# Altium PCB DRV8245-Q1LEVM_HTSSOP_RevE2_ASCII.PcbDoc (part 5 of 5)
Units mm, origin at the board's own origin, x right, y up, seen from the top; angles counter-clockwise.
Board outline 81.9 x 103.6 mm, 4 copper layers (Top Layer, Signal Layer 1, Signal Layer 2, Bottom Layer), stack 1.554 mm thick; 187 components, 116 nets, 590 pads, 1182 vias.
Unrouted connection lines stored in the file: 116.
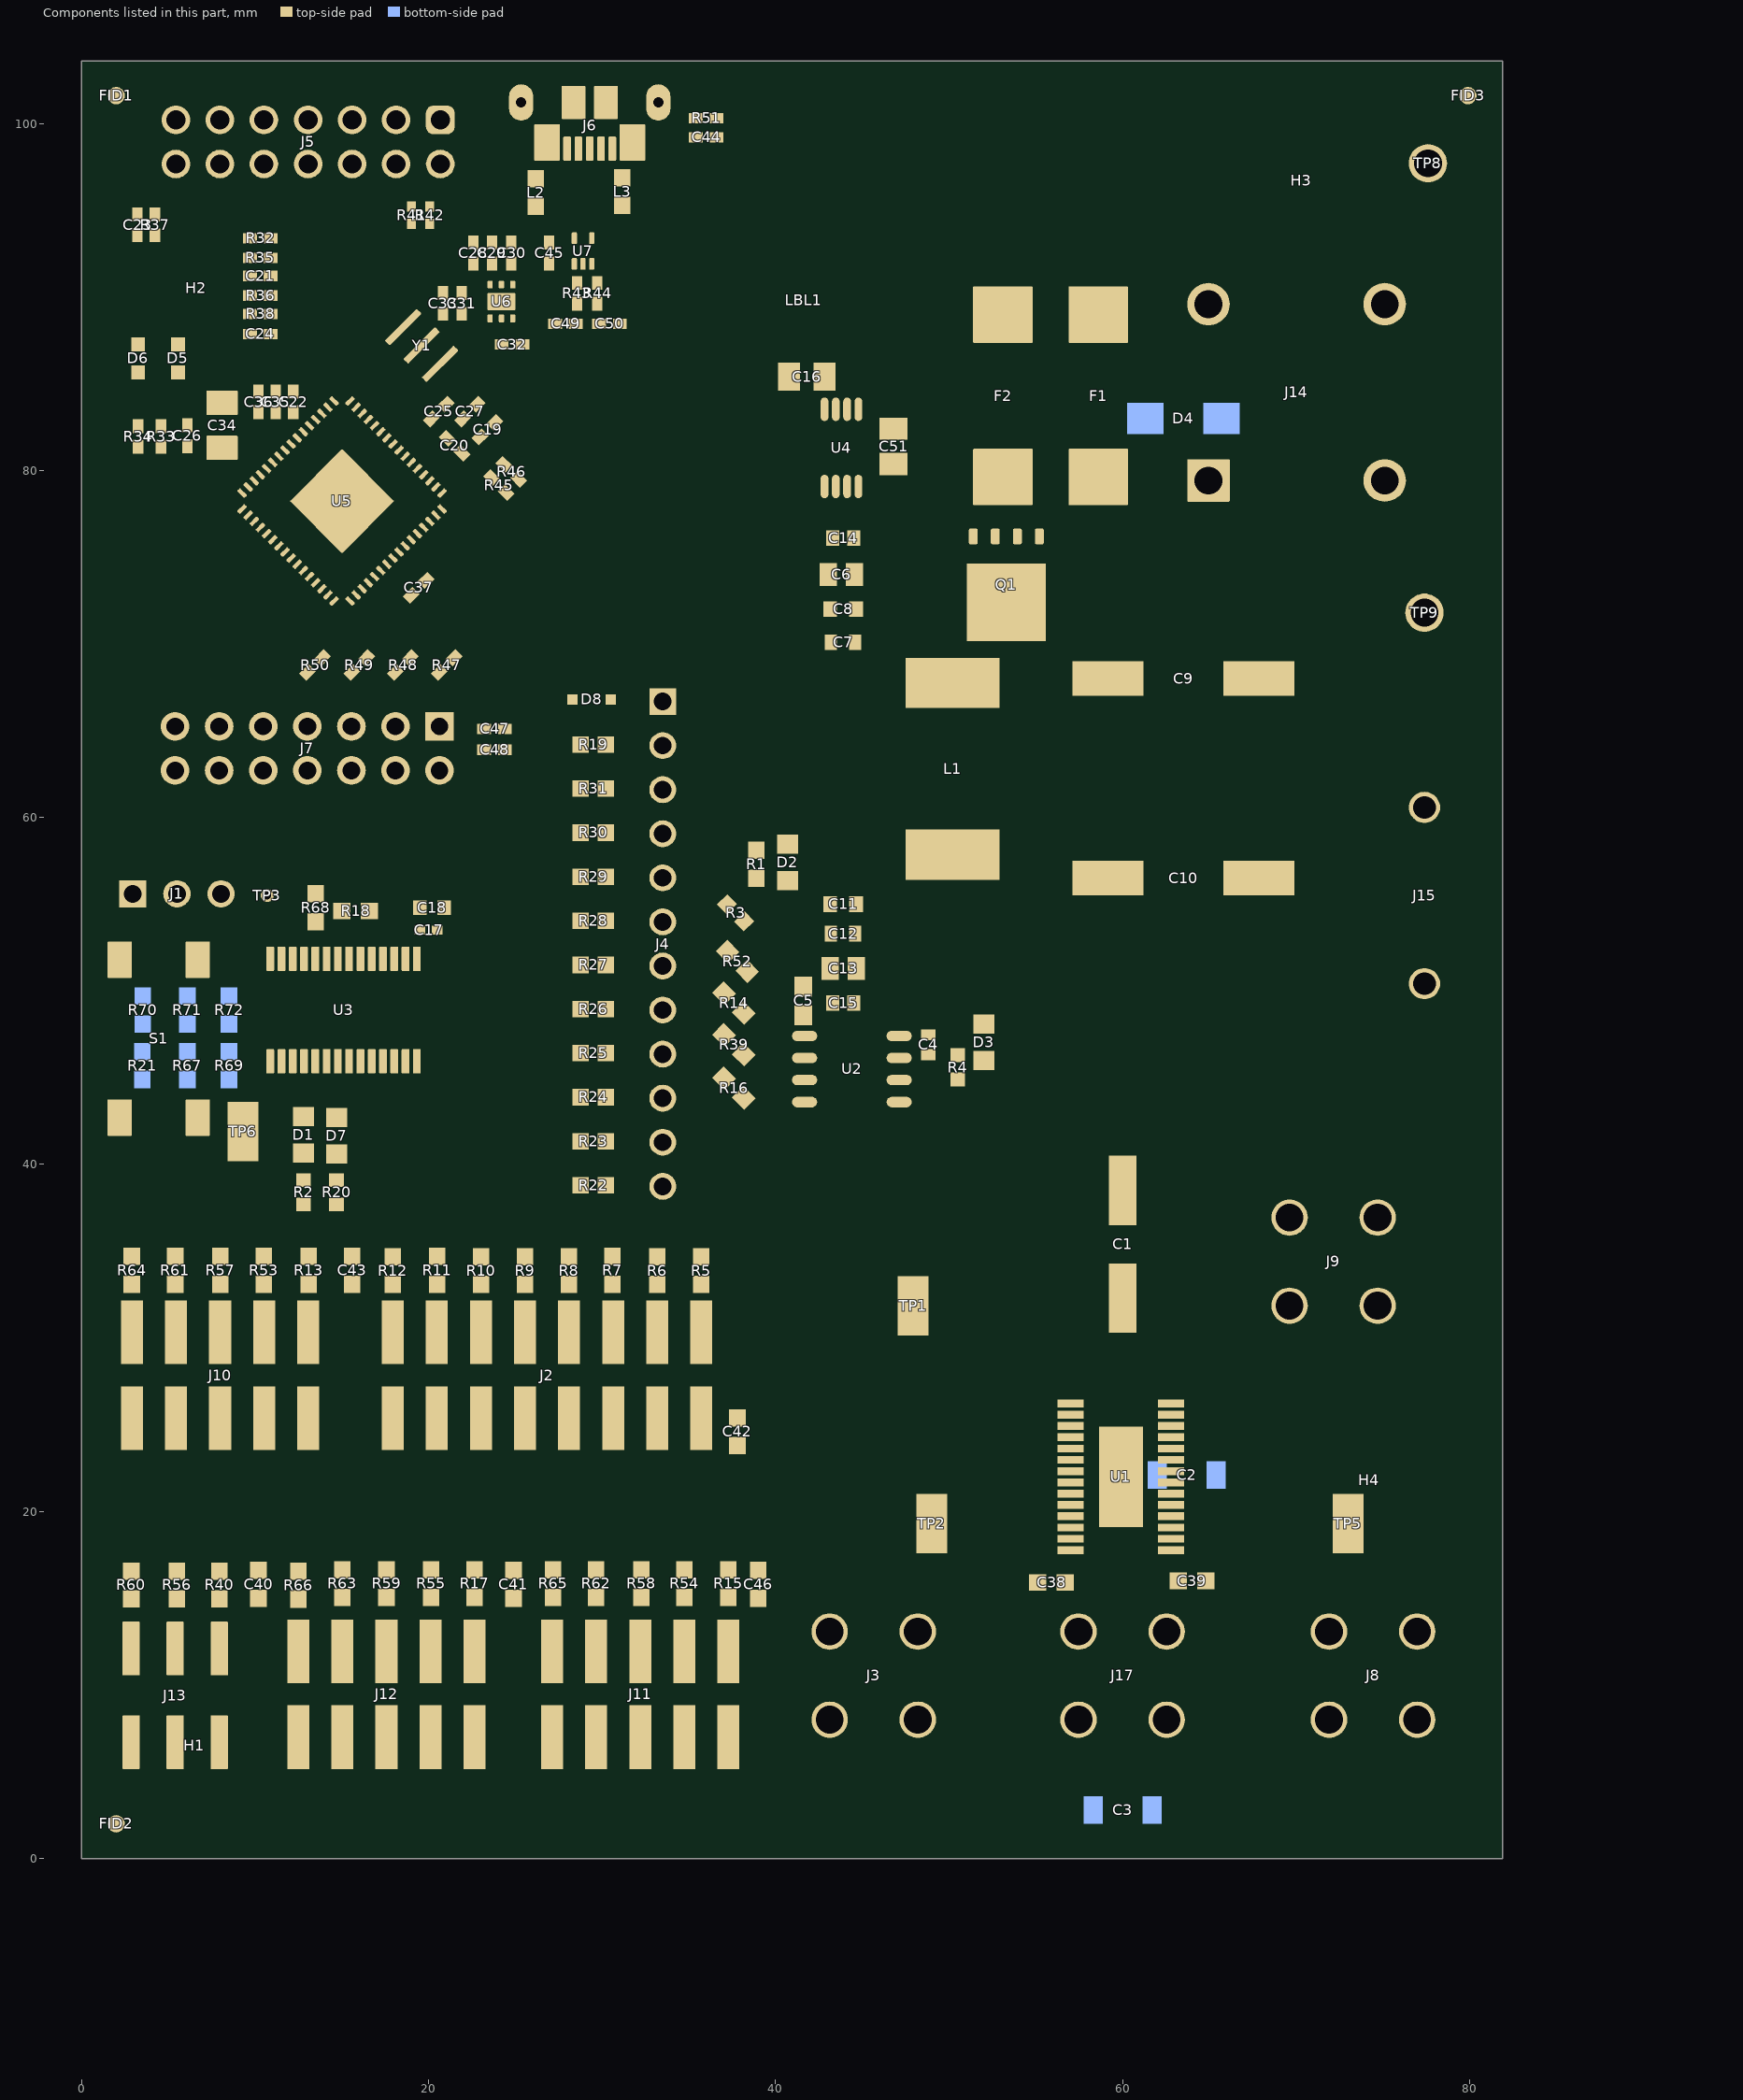
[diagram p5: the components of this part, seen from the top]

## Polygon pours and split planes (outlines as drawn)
VM on Top Layer "TOP_LAYER_NONET_P-001" (solid, pour order 239): 52.9,47.1 56.1,47.1 56.1,43.7
VM on Top Layer "TOP_LAYER_VM_P125" (solid, pour order 125): 40,21.5 80,21.5 80,42 63.2,42 63.2,60.5 44,60.5 44,47.1 56.1,47.1 56.1,42 40,42
GND on Top Layer "TOP_LAYER_GND_P237" (solid, remove dead copper, pour order 237): 0,0 81.9,0 81.9,103.6 0,103.6
GND on Top Layer "TOP_LAYER_GND_P086" (solid, pour order 86): 56,35.5 63.9,35.5 63.9,2 56,2
OUT2 on Top Layer "TOP_LAYER_OUT2_P173" (solid, pour order 173): 62.1,21.4 62.1,19.4 63.9,19.4 63.9,2 80,2 80,21.4
OUT1 on Top Layer "TOP_LAYER_OUT1_P129" (solid, pour order 129): 58,21.3 58,19.4 56,19.4 56,2 39.9,2 39.9,21.3
P_IN on Top Layer "TOP_LAYER_P_IN_P227" (solid, pour order 227): 63.2,60.7 63.2,79.8 44,79.8 44,60.7
VBAT on Top Layer "TOP_LAYER_VBAT_P223" (solid, pour order 223): 63.2,84.4 63.2,75.3 48.3,75.3 48.3,84.4
NetF1_2 on Top Layer "TOP_LAYER_NETF1_2_P207" (solid, pour order 207): 48.2,84.5 78.8,84.5 78.8,99.4 48.2,99.4
EZFET_USB_Shield on Top Layer "TOP_LAYER_EZFET_USB_SHIELD_P201" (solid, remove dead copper, pour order 201): 23.799,103.312 35.891,103.312 35.891,98.032 23.799,98.032
VM on Bottom Layer "TOP_LAYER_NONET_P-001" (solid, pour order 80): 44.1,60.1 63.2,60.1 63.2,52.9 46.1,52.9 44.1,54.9
GND on Bottom Layer "BOTTOM_LAYER_GND_P204" (solid, pour order 204): 56.2,3.8 56.2,35.5 63.8,35.5 63.8,3.8
OUT2 on Bottom Layer "BOTTOM_LAYER_OUT2_P211" (solid, pour order 211): 61.1,2.05 80,2.05 80,21 63.9,21 63.9,3.6 61.1,3.6
OUT1 on Bottom Layer "BOTTOM_LAYER_OUT1_P205" (solid, pour order 205): 58.9,2.05 58.9,3.6 56,3.6 56,21 40,21 40,2.05
P_IN on Bottom Layer "BOTTOM_LAYER_P_IN_P174" (solid, pour order 174): 63.2,60.28 63.2,79.8 44.1,79.8 44.1,60.28
NetF1_2 on Bottom Layer "BOTTOM_LAYER_NETF1_2_P203" (solid, pour order 203): 48.2,84.5 78.8,84.5 78.8,99.4 48.2,99.4
VBAT on Bottom Layer "BOTTOM_LAYER_VBAT_P165" (solid, pour order 165): 62.9,84.4 62.9,75.3 48.3,75.3 48.3,84.4
GND on Bottom Layer "BOTTOM_LAYER_GND_P241" (solid, remove dead copper, pour order 241): 0,0 81.9,0 81.9,103.6 0,103.6
VM on Bottom Layer "BOTTOM_LAYER_VM_P235" (solid, pour order 235): 40,21 80,21 80,42.05 40,42.05
EZFET_USB_Shield on Bottom Layer "BOTTOM_LAYER_EZFET_USB_SHIELD_P219" (solid, remove dead copper, pour order 219): 23.799,103.312 35.891,103.312 35.891,98.032 23.799,98.032
GND on Signal Layer 2 "SIGNAL_LAYER_2_GND_P199" (solid, pour order 199): 0,0 81.9,0 81.9,103.6 0,103.6
P_IN on Signal Layer 2 "SIGNAL_LAYER_2_P_IN_P198" (solid, pour order 198): 63.2,60.28 63.2,79.8 44.1,79.8 44.1,60.28
VBAT on Signal Layer 2 "SIGNAL_LAYER_2_VBAT_P197" (solid, pour order 197): 62.9,84.4 62.9,75.3 48.3,75.3 48.3,84.4
NetF1_2 on Signal Layer 2 "SIGNAL_LAYER_2_NETF1_2_P196" (solid, pour order 196): 48.2,84.5 78.8,84.5 78.8,99.4 48.2,99.4
3V3 on Signal Layer 2 "SIGNAL_LAYER_2_3V3_P194" (solid, pour order 194): 31.8,65.4 32,65.2 41,65.2 41,36.8 32,36.8
3V3_MCU on Signal Layer 2 "SIGNAL_LAYER_2_3V3_MCU_P192" (solid, pour order 192): 0,63.6 24.2,63.6 24.2,67.7 29.6,67.7 29.6,36.9 0,36.9
VM on Signal Layer 2 "SIGNAL_LAYER_2_VM_P177" (solid, pour order 177): 55,43 55,41.4 65,41.4 65,43
VM on Signal Layer 2 "SIGNAL_LAYER_2_VM_P175" (solid, pour order 175): 41.1,42.3 65,42.3 65,60.1 41.1,60.1
VM on Signal Layer 2 "SIGNAL_LAYER_2_VM_P160" (solid, pour order 160): 80,42 80,2 40,2 40,42
EZFET_VBUS on Signal Layer 2 "SIGNAL_LAYER_2_EZFET_VBUS_P136" (solid, remove dead copper, pour order 136): 20.124,103.311 35.89,103.311 35.891,103.312 35.992,103.212 35.992,89.393 20.159,89.393
EZFET_VCC on Signal Layer 2 "SIGNAL_LAYER_2_EZFET_VCC_P132" (solid, remove dead copper, pour order 132): 0.228,63.978 23.822,63.978 23.822,89.531 20.127,89.531 20.124,89.534 20.124,103.311 0.255,103.311 0.228,103.338
GND on Signal Layer 1 "TOP_LAYER_NONET_P-001" (solid, pour order 225): 40,42 80,42 80,2 40,2
GND on Signal Layer 1 "SIGNAL_LAYER_1_GND_P190" (solid, pour order 190): 55,41 55,43 65,43 65,41
GND on Signal Layer 1 "SIGNAL_LAYER_1_GND_P184" (solid, pour order 184): 0.2,103.7 82,103.7 81.9,103.6 81.9,42.2 39.5,42.2 39.5,0 -0.305,0

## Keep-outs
Keep-Out Layer:
  text ".Layer_Name" at 14.656,-21.806 h1.52

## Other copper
Top Layer:
  text ".Layer_Name" at 14.656,-21.806 h1.52
Bottom Layer:
  text ".Layer_Name" at 14.656,-21.806 h1.52

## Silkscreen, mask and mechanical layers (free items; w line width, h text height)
Top Overlay:
  lines w0.1: 80,2 80,2
  lines w0.2: 40,2 40,42 80,42 80,2 40,2
  lines w0.254: 19.8,101.7 22.1,101.7 22.1,99.3
  text "For EZFET-LITE Flashing Only" at 7.266,101.814 h1
  text "1" at 22.5,101.4 h0.6
  text "+BAT" at 71.7,97.2 h1.52
  text "'.PRJ_Number'.PCB_Rev" at 34,93.2 h2.75
  text "PWR" at 2.211,84.207 h1
  text "MODE" at 4.578,84.208 h1
  text "GND" at 71.9,71.3 h1.52
  text "GND" at 35.6,66.2 h1.52
  text "3V3" at 35.7,63.7 h1.52
  text "GND" at 4.778,61.108 h1.85 r270
  text "3V3" at 9.9,61.108 h1.85 r270
  text ">>RX" at 12.5,61.108 h1.85 r270
  text "<<TX" at 15,61.108 h1.85 r270
  text "TDIO" at 17.5,61.108 h1.85 r270
  text "TCK" at 20.1,61.108 h1.85 r270
  text "nSLEEP" at 22.8,61.1 h1.52
  text "nFAULT" at 37.5,59.7 h1.52
  text "IPROPI" at 23.431,58.6 h1.52
  text "nFAULT" at 22.845,56.1 h1.52
  text "SDO" at 24.968,53.6 h1.52
  text "GND" at 76.3,53.5 h1.85 r90
  text "RST" at 2.2,53.4 h0.8
  text "PUSH" at 7.3,53.4 h0.8
  text "SDI" at 25.709,51 h1.52
  text "VM" at 51,48.9 h1.52
  text "SCLK" at 24.304,48.4 h1.52
  text "nSCS" at 24.4,45.9 h1.52
  text "PH/IN2" at 23.585,43.4 h1.52
  text "EN/IN1" at 23.766,40.7 h1.52
  text "DRV8245 HTSSOP" at 40.6,40.7 h1.52
  text "3V3" at 16.7,40.6 h1.52 r90
  text "Status" at 11.7,39.9 h1.52 r90
  text "40mm x 40mm" at 40.9,39.6 h1
  text "4 layers" at 40.9,38.7 h1
  text "DRVOFF" at 22.368,38.3 h1.52
  text "2oz copper" at 40.9,37.8 h1
  text "VM" at 65.7,33.8 h1.52
  text "VM" at 49.3,32.7 h1 r270
  text "." at 55.5,26.7 h1.52
  text "680" at 32.49,21.328 h1.2 r45
  text "470" at 35.03,21.328 h1.2 r45
  text "6.8k" at 17.25,21.074 h1.2 r45
  text "4.7k" at 19.79,21.074 h1.2 r45
  text "3.3k" at 22.33,21.074 h1.2 r45
  text "2.2k" at 24.87,21.074 h1.2 r45
  text "1.5k" at 27.41,21.074 h1.2 r45
  text "1.0k" at 29.95,21.074 h1.2 r45
  text "LVL4" at 4.3,21 h1.2 r45
  text "LVL3" at 6.9,21 h1.2 r45
  text "LVL5" at 1.8,20.9 h1.2 r45
  text "LVL2" at 9.4,20.9 h1.2 r45
  text "LVL1" at 11.9,20.9 h1.2 r45
  text "ITRIP" at 6.2,19.1 h1.85
  text "IPROPI" at 24.892,18.796 h1.85
  text "OUT2" at 43.7,16.8 h1.52
  text "OUT1" at 71.5,16.1 h1.52
  text "GND" at 58.6,15.3 h1.52
  text "LVL3" at 1.8,2.7 h1.2 r45
  text "LVL4" at 14,2.7 h1.2 r45
  text "LVL3" at 16.6,2.7 h1.2 r45
  text "LVL4" at 28.7,2.7 h1.2 r45
  text "LVL3" at 31.3,2.7 h1.2 r45
  text "LVL2" at 4.3,2.6 h1.2 r45
  text "LVL1" at 6.8,2.6 h1.2 r45
  text "LVL5" at 11.5,2.6 h1.2 r45
  text "LVL2" at 19.1,2.6 h1.2 r45
  text "LVL1" at 21.6,2.6 h1.2 r45
  text "LVL5" at 26.2,2.6 h1.2 r45
  text "LVL2" at 33.8,2.6 h1.2 r45
  text "LVL1" at 36.3,2.6 h1.2 r45
  text "MODE" at 3,1 h1.85
  text "SLEW RATE" at 12.9,1 h1.85
  text "DIAG" at 30.2,1 h1.85
  text ".Layer_Name" at 14.656,-21.806 h1.52
Bottom Overlay:
  text "ID1" at 4.4,51 h1.52
  text "ID2" at 6.8,51 h1.52
  text "ID3" at 9.3,51 h1.52
  text "0" at 10.3,48.5 h1.52
  text "1" at 10.3,45.2 h1.52
  text ".Layer_Name" at 14.656,-21.806 h1.52
Top Paste:
  text ".Layer_Name" at 14.656,-21.806 h1.52
Bottom Paste:
  text ".Layer_Name" at 14.656,-21.806 h1.52
Top Solder:
  text ".Layer_Name" at 14.656,-21.806 h1.52
  text ".Layer_Name" at 14.656,-21.806 h1.52
Bottom Solder:
  text ".Layer_Name" at 14.656,-21.806 h1.52
Drill Guide:
  text ".Layer_Name" at 14.656,-21.806 h1.52
M1 Board Outline:
  lines w0.2: 81.7,0 81.7,103.477
  lines w0.254: 81.7,0 0,0 0,103.533 81.7,103.477
  text ".Layer_Name" at 14.656,-21.806 h1.52
M2 Board Dimensions:
  rectangle: 0,-6.985 3.175,-3.81
  rectangle: 3.175,-10.16 12.7,-6.985
  lines w0.178: 0,-6.985 25.4,-6.985 ; 3.175,-10.16 3.175,-3.81 ; 6.35,-10.16 6.35,-3.81 ; 12.7,-10.16 12.7,-3.81 ; 19.05,-10.16 19.05,-3.81 ; 0,-10.16 25.4,-10.16 25.4,-3.81 0,-3.81 0,-10.16
  text ".Layer_Name" at 14.656,-21.806 h1.52
M3 3D STEP Top:
  text ".Layer_Name" at 14.656,-21.806 h1.52
M4 3D STEP Bottom:
  text ".Layer_Name" at 14.656,-21.806 h1.52
M5 Assembly Top:
  lines w0.254: -7.417,-23.626 160.223,-23.626 ; -7.417,-18.462 160.274,-18.462 ; -7.417,-13.297 -7.417,-28.791 94.31,-28.791 160.274,-28.791 160.274,-13.297 -7.404,-13.297 -7.404,-28.791 32.614,-28.791 ; 55.194,-28.791 55.194,-13.297 ; 87.376,-18.462 87.376,-13.297 ; 108.712,-18.462 108.712,-13.297 ; 124.511,-28.956 124.511,-23.804
  text "COMPONENTS MARKED 'DNP' SHOULD NOT BE POPULATED." at 29.299,-8.09 h1.52
  text "ASSEMBLY VARIANT:" at 29.286,-11.024 h1.52
  text ".VariantName" at 55.601,-11.024 h1.52
  text "PCB VIEWED FROM TOP SIDE" at -5.804,-16.654 h1.52
  text "BOARD #:" at 57.099,-16.654 h1.52
  text ".PRJ_Number" at 70.955,-16.654 h1.52
  text "REV:" at 92.405,-16.654 h1.52
  text ".PCB_Rev" at 99.809,-16.654 h1.52
  text "SVN REV:" at 113.69,-16.654 h1.52
  text ".VersionControl_RevNumber" at 126.543,-16.654 h1.52
  text "TID #:" at 57.099,-21.819 h1.52
  text ".TID" at 70.955,-21.819 h1.52
  text "PLOT NAME =" at -5.804,-27.034 h1.52
  text ".plot_File_Name" at 14.656,-27.034 h1.52
  text "GENERATED    :" at 57.15,-27.034 h1.52
  text ".Print_Date" at 79.235,-27.034 h1.52
  text ".Print_Time" at 97.752,-27.034 h1.52
  text "TEXAS INSTRUMENTS" at 129.87,-27.034 h1.52
M6 Assembly Bottom:
  lines w0.254: -7.429,-18.474 160.261,-18.474 ; -7.379,-23.639 160.261,-23.639 ; 28.334,-28.969 28.334,-23.817 ; 44.133,-18.474 44.133,-13.31 ; 65.468,-18.474 65.468,-13.31 ; 97.65,-28.804 97.65,-13.31 ; 120.231,-28.804 160.249,-28.804 160.249,-13.31 -7.429,-13.31 -7.429,-28.804 58.534,-28.804 160.261,-28.804 160.261,-13.31
  text "COMPONENTS MARKED 'DNP' SHOULD NOT BE POPULATED." at 154.991,-8.077 h1.52
  text ".VariantName" at 128.473,-11.024 h1.52
  text "ASSEMBLY VARIANT:" at 154.864,-11.024 h1.52
  text ".VersionControl_RevNumber" at 26.302,-16.667 h1.52
  text "SVN REV:" at 39.154,-16.667 h1.52
  text ".PCB_Rev" at 53.035,-16.667 h1.52
  text "REV:" at 60.439,-16.667 h1.52
  text ".PRJ_Number" at 81.89,-16.667 h1.52
  text "BOARD #:" at 95.745,-16.667 h1.52
  text "PCB VIEWED FROM BOTTOM SIDE" at 158.648,-16.667 h1.52
  text ".TID" at 81.89,-21.831 h1.52
  text "TID #:" at 95.745,-21.831 h1.52
  text "TEXAS INSTRUMENTS" at 22.974,-27.047 h1.52
  text ".Print_Time" at 55.093,-27.047 h1.52
  text ".Print_Date" at 73.609,-27.047 h1.52
  text "GENERATED    :" at 95.694,-27.047 h1.52
  text ".plot_File_Name" at 138.189,-27.047 h1.52
  text "PLOT NAME =" at 158.648,-27.047 h1.52
M9 Title Sheet:
  lines w0.254: -12.484,26.454 -7.404,26.454 ; -12.484,86.779 -7.404,86.779 ; -12.484,147.104 -7.404,147.104 ; 51.016,-33.871 51.016,-28.791 ; 51.016,202.349 51.016,207.429 ; 114.516,-33.871 114.516,-28.791 ; 114.516,202.349 114.516,207.429 ; 160.553,-28.791 160.553,-13.297 287.109,-13.297 ; 178.016,-33.871 178.016,-28.791 ; 178.016,202.349 178.016,207.429 ; 241.516,-33.871 241.516,-28.791 ; 241.516,202.349 241.516,207.429 ; 287.109,-28.791 287.109,-13.297 ; 287.109,-20.917 363.309,-20.917 ; 287.109,-5.677 363.309,-5.677 ; 287.134,9.411 363.334,9.411 ; 305.016,-33.871 305.016,-28.791 ; 305.016,202.349 305.016,207.429 ; 325.336,-28.537 325.336,-13.297 ; 363.309,-13.297 287.109,-13.297 ; 363.309,1.943 287.109,1.943 ; 363.436,1.689 363.436,-28.791 ; 363.436,22.123 287.134,22.123 287.109,22.123 287.109,9.411 287.109,1.943 ; 363.436,26.454 368.516,26.454 ; 363.436,86.779 368.516,86.779 ; 363.436,147.104 368.516,147.104 ; 287.109,-13.297 287.109,1.943 ; 363.436,-28.791 363.436,202.349 -7.404,202.349 -7.404,-28.791 363.436,-28.791 ; -12.484,-33.871 -12.484,207.429 368.516,207.429 368.516,-33.871 -12.484,-33.871
  text "1" at 18.792,204.127 h1.78
  text "2" at 82.182,204.127 h1.78
  text "3" at 145.411,204.127 h1.78
  text "4" at 209.08,204.127 h1.78
  text "5" at 272.555,204.127 h1.78
  text "6" at 336.182,204.127 h1.78
  text "A" at -10.579,175.095 h1.78
  text "A" at 365.341,175.095 h1.78
  text "B" at -10.579,114.643 h1.78
  text "B" at 365.341,114.643 h1.78
  text "C" at -10.579,54.318 h1.78
  text "C" at 365.341,54.318 h1.78
  text "PROJECT TITLE:" at 288.125,7.048 h1.14
  text ".PRJ_Title" at 289.395,3.662 h1.78
  text "DESIGNED FOR:" at 288.125,-0.597 h1.14
  text ".PRJ_Customer" at 289.395,-4.153 h1.78
  text "D" at -10.579,-5.88 h1.78
  text "D" at 365.341,-5.88 h1.78
  text "FILE NAME:" at 288.125,-8.217 h1.14
  text ".PCB_File_Name_No_Path" at 289.395,-11.265 h1.78
  text "Texas Instruments (TI) and/or its licensors do not warrant the accuracy or completeness of this specification" at 161.9,-15.376 h1.14
  text "ENGINEER:" at 288.125,-15.583 h1.14
  text "LAYOUT BY:" at 326.352,-15.583 h1.14
  text "or any information contained therein. TI and/or its licensors do not warrant that this design will meet" at 160.757,-18.237 h1.14
  text ".PRJ_Engineer" at 289.395,-19.52 h1.78
  text ".PCB_Layout" at 327.635,-19.52 h1.78
  text "the specifications, will be suitable for your application or fit for any particular purpose, or will operate in" at 160.757,-21.099 h1.14
  text ".Layer_Name" at 14.656,-21.806 h1.52
  text "ALTIUM DESIGNER VERSION:" at 326.352,-23.457 h1.14
  text "an implementation. TI and/or its licensors do not warrant that the design is production worthy. You should" at 160.757,-23.961 h1.14
  text "completely validate and test your design implementation to confirm the system functionality for your application." at 161.9,-26.822 h1.14
  text ".print_Scale" at 289.395,-26.843 h1.78
  text ".Application_BuildNumber" at 327.635,-26.843 h1.78
  text "1" at 18.792,-32.093 h1.78
  text "2" at 82.182,-32.093 h1.78
  text "3" at 145.411,-32.093 h1.78
  text "4" at 209.08,-32.093 h1.78
  text "5" at 272.555,-32.093 h1.78
  text "6" at 336.182,-32.093 h1.78
M10 Fab Notes:
  drawing of 189 lines, arcs and shapes, not listed
  text "DESIGN INFORMATION" at 314.503,161.447 h1.52
  text "MIN. TRACK WIDTH:" at 298.131,158.091 h1.52
  text "8" at 325.976,158.091 h1.52
  text "MIL" at 329.907,158.091 h1.52
  text "MIN. CLEARANCE:" at 298.131,154.938 h1.52
  text "0.2" at 324.452,154.938 h1.52
  text "mm" at 329.907,154.938 h1.52
  text "MIN. VIA PAD SIZE:" at 298.131,151.785 h1.52
  text "24" at 325.214,151.785 h1.52
  text "MIL" at 329.907,151.785 h1.52
  text "0.05mm (2MIL)" at 315.784,148.486 h1.52
  text "MINIMUM ANNULAR RING" at 289.769,148.277 h1.52
  text "EXTERNAL" at 333.768,148.277 h1.52
  text "PER" at 294.849,145.48 h1.52
  text "IPC-D-275 CLASS 2 LEVEL C" at 300.437,145.48 h1.52
  text "MIL, HOLES" at 338.238,142.928 h1.52
  text "+/-" at 328.27,142.709 h1.52
  text "+/-" at 349.961,142.709 h1.52
  text "REGISTRATION TOLERANCES:" at 289.769,142.682 h1.52
  text "METAL" at 320.243,142.682 h1.52
  text "5" at 334.879,142.683 h1.52
  text "3" at 356.037,142.683 h1.52
  text "MIL" at 358.99,142.682 h1.52
  text "HOLE SIZE TOLERANCE (UNLESS OTHERWISE SPECIFIED):" at 289.769,140.185 h1.52
  text "+/-" at 349.961,140.112 h1.52
  text "3" at 356.037,140.085 h1.52
  text "MIL" at 358.99,140.085 h1.52
  text "MATERIAL:" at 287.87,136.589 h1.52
  text "FR-4 High Tg" at 312.926,133.324 h1.52
  text "X" at 309.257,133.122 h1.52
  text "FR-408" at 298.563,133.007 h1.52
  text "OTHER" at 336.358,133.007 h1.52
  text "62 MIL (1.6mm) +/-10%" at 306.694,129.374 h1.52
  text "X" at 303.643,129.312 h1.52
  text "THICKNESS:" at 289.769,129.165 h1.52
  text "OTHER" at 339.33,129.165 h1.52
  text "TOLERANCE:" at 289.769,125.652 h1.52
  text "X" at 311.314,125.652 h1.52
  text "ANSI IPC-6012 TYPE 3 CLASS 2" at 315.836,125.652 h1.52
  text "OTHER +/-" at 315.835,121.989 h1.52
  text "BOW & TWIST:" at 289.769,118.302 h1.52
  text "X" at 311.314,118.302 h1.52
  text "ANSI IPC-6012 TYPE 3 CLASS 2" at 315.836,118.302 h1.52
  text "OTHER +/-" at 315.835,114.576 h1.52
  text "DRILLING:" at 287.87,111.258 h1.52
  text "NC_DRILL FILES" at 332.599,108.586 h1.52
  text "REFERENCE:" at 289.769,108.486 h1.52
  text "X" at 306.463,108.484 h1.52
  text "AS SHOWN" at 310.984,108.486 h1.52
  text "X" at 329.348,108.486 h1.52
  text "OTHER" at 340.168,104.873 h1.52
  text "PTH COPPER THICKNESS:" at 289.761,104.783 h1.52
  text "X" at 318.697,104.783 h1.52
  text "20-30 um" at 321.948,104.783 h1.52
  text "BOARD FINISH:" at 287.87,101.034 h1.52
  text "SILKSCREEN:" at 291.812,98.237 h1.52
  text "X" at 316.14,98.237 h1.52
  text "TOP" at 319.112,98.237 h1.52
  text "X" at 329.094,98.237 h1.52
  text "BOTTOM" at 332.091,98.237 h1.52
  text "SILKSCREEN COLOR:" at 291.812,94.295 h1.52
  text "X" at 316.115,94.295 h1.52
  text "WHITE" at 319.112,94.295 h1.52
  text "OTHER" at 332.091,94.295 h1.52
  text "X" at 319.442,90.652 h1.52
  text "GREEN" at 322.439,90.652 h1.52
  text "OTHER" at 338.136,90.652 h1.52
  text "SOLDER RESIST COLOR:" at 291.812,90.477 h1.52
  text "X" at 319.442,86.734 h1.52
  text "MATTE" at 322.439,86.734 h1.52
  text "SEMI-GLOSS" at 338.125,86.717 h1.52
  text "IMMERSION GOLD (ENIG)" at 314.819,82.345 h1.52
  text "ENEPIG" at 348.793,82.162 h1.52
  text "SURFACE FINISH:" at 287.87,82.136 h1.52
  text "X" at 310.298,82.136 h1.52
  text "IMM. TIN/SILVER OR EQUIV" at 296.24,78.649 h1.52
  text "OTHER" at 332.599,78.549 h1.52
  text "ARRAY/PANEL:" at 287.87,74.602 h1.52
  text "CUT AND TRIM PER M1 BOARD OUTLINE" at 314.819,74.393 h1.52
  text "N.C. ROUTE" at 314.819,70.94 h1.52
  text "X" at 332.295,70.94 h1.52
  text "V. SCORE" at 336.816,70.94 h1.52
  text "CERTIFICATION:" at 287.87,67.66 h1.52
  text "MATERIALS AND WORKMANSHIP FOR ALL PCBS" at 306.285,67.66 h1.52
  text "TO MEET OR EXCEED THE REQUIREMENTS OF:" at 306.285,65.271 h1.52
  text "X" at 297.078,62.003 h1.52
  text "ANSI IPC-A-600F CLASS ->" at 300.329,62.003 h1.52
  text "X" at 342.188,62.003 h1.52
  text "2" at 344.982,62.003 h1.52
  text "1" at 336.981,61.965 h1.52
  text "3" at 353.973,61.965 h1.52
  text "X" at 317.702,58.252 h1.52
  text "RoHS" at 320.953,58.252 h1.52
  text "OTHER" at 337.321,58.252 h1.52
  text "PER ORDER" at 347.407,58.252 h1.52
  text "ALL BOARDS MUST MEET OR EXCEED UL94-V0 REQUIREMENTS." at 288.569,54.345 h1.52
  text "PCB MUST BEAR THE UL94V-0 UL REGISTERED MATERIAL ID NUMBER" at 288.569,51.397 h1.52
  text "ADDITIONAL REQUIREMENTS:" at 287.87,47.094 h1.52
  text "MICROSECTION:" at 289.769,44.373 h1.52
  text "YES" at 312.775,44.373 h1.52
  text "REQUIRED" at 334.657,40.707 h1.52
  text "BARE BOARD ELEC. TEST:" at 289.769,40.634 h1.52
  text "NONE" at 322.935,40.634 h1.52
  text "X" at 331.66,40.634 h1.52
  text "PER ORDER" at 349.693,40.634 h1.52
  text "XX MIL VIAS REQUIRE NON-CONDUCTIVE FILL AND PLANARIZE" at 294.04,35.428 h1.5
  text "XX MIL VIAS REQUIRE CONDUCTIVE FILL AND PLANARIZE" at 294.243,32.787 h1.52
  text "OUTER XX MIL TRACES REQUIRE 50 OHM SINGLE-ENDED IMPEDANCE" at 294.218,28.637 h1.47
  text "LAYER 2 & 3 (INNER LAYERS) XX MIL WIDE, XX MIL SPACE / TRACES REQUIRE 100 OHM DIFFERENTIAL IMPEDANCE" at 294.015,22.65 h1.52
  text ".Layer_Name" at 14.656,-21.806 h1.52
M11 Gerber Information:
  lines w0.254: -7.417,-23.626 160.223,-23.626 ; -7.417,-18.462 160.274,-18.462 ; -7.417,-13.297 -7.417,-28.791 94.31,-28.791 160.274,-28.791 160.274,-13.297 -7.404,-13.297 -7.404,-28.791 32.614,-28.791 ; 55.194,-28.791 55.194,-13.297 ; 87.376,-18.462 87.376,-13.297 ; 108.712,-18.462 108.712,-13.297 ; 124.511,-28.956 124.511,-23.804
  text "ALL ARTWORK VIEWED FROM TOP SIDE" at -5.804,-16.654 h1.52
  text "BOARD #:" at 57.099,-16.654 h1.52
  text ".PRJ_Number" at 70.955,-16.654 h1.52
  text "REV:" at 92.405,-16.654 h1.52
  text ".PCB_Rev" at 99.809,-16.654 h1.52
  text "SVN REV:" at 113.69,-16.654 h1.52
  text ".VersionControl_RevNumber" at 126.543,-16.654 h1.52
  text "LAYER NAME =" at -5.804,-21.806 h1.52
  text "TID #:" at 57.099,-21.819 h1.52
  text ".TID" at 70.955,-21.819 h1.52
  text "PLOT NAME =" at -5.804,-27.034 h1.52
  text ".plot_File_Name" at 14.656,-27.034 h1.52
  text "GENERATED    :" at 57.15,-27.034 h1.52
  text ".Print_Date" at 79.235,-27.034 h1.52
  text ".Print_Time" at 97.752,-27.034 h1.52
  text "TEXAS INSTRUMENTS" at 129.87,-27.034 h1.52
M12 Stackup:
  drawing of 295 lines, arcs and shapes, not listed
  text "Layer" at 146.288,26.15 h1.52
  text "Name" at 156.7,26.15 h1.52
  text "Material" at 180.569,26.15 h1.52
  text "Thickness" at 202.408,26.15 h1.52
  text "Constant" at 218.913,26.15 h1.52
  text "Board Layer Stack" at 233.388,26.15 h1.52
  text "1" at 146.288,23.102 h1.52
  text "Top Overlay" at 156.7,23.102 h1.52
  text "2" at 146.288,20.054 h1.52
  text "Top Solder" at 156.7,20.054 h1.52
  text "Solder Resist" at 180.569,20.054 h1.52
  text "0.40mil" at 202.408,20.054 h1.52
  text "3.5" at 218.913,20.054 h1.52
  text "3" at 146.288,17.006 h1.52
  text "Top Layer" at 156.7,17.006 h1.52
  text "Copper" at 180.569,17.006 h1.52
  text "2.80mil" at 202.408,17.006 h1.52
  text "4" at 146.288,13.958 h1.52
  text "Dielectric 1" at 156.7,13.958 h1.52
  text "FR4 370" at 180.569,13.958 h1.52
  text "11.40mil" at 202.408,13.958 h1.52
  text "4.2" at 218.913,13.958 h1.52
  text "5" at 146.288,10.91 h1.52
  text "Signal Layer 1" at 156.7,10.91 h1.52
  text "Copper" at 180.569,10.91 h1.52
  text "1.40mil" at 202.408,10.91 h1.52
  text "6" at 146.288,7.862 h1.52
  text "Dielectric 2" at 156.7,7.862 h1.52
  text "FR4 370" at 180.569,7.862 h1.52
  text "30.00mil" at 202.408,7.862 h1.52
  text "4.2" at 218.913,7.862 h1.52
  text "7" at 146.288,4.814 h1.52
  text "Signal Layer 2" at 156.7,4.814 h1.52
  text "Copper" at 180.569,4.814 h1.52
  text "1.40mil" at 202.408,4.814 h1.52
  text "8" at 146.288,1.766 h1.52
  text "Dielectric 3" at 156.7,1.766 h1.52
  text "FR4 370" at 180.569,1.766 h1.52
  text "11.40mil" at 202.408,1.766 h1.52
  text "4.2" at 218.913,1.766 h1.52
  text "9" at 146.288,-1.282 h1.52
  text "Bottom Layer" at 156.7,-1.282 h1.52
  text "Copper" at 180.569,-1.282 h1.52
  text "2.80mil" at 202.408,-1.282 h1.52
  text "10" at 146.288,-4.33 h1.52
  text "Bottom Solder" at 156.7,-4.33 h1.52
  text "Solder Resist" at 180.569,-4.33 h1.52
  text "0.40mil" at 202.408,-4.33 h1.52
  text "3.5" at 218.913,-4.33 h1.52
  text "11" at 146.288,-7.378 h1.52
  text "Bottom Overlay" at 156.7,-7.378 h1.52
  text ".Layer_Name" at 14.656,-21.806 h1.52
M13 Component Bodies Top:
  text ".Layer_Name" at 14.656,-21.806 h1.52
M14 Component Bodies Bottom:
  text ".Layer_Name" at 14.656,-21.806 h1.52
M15 Courtyards Top:
  text ".Layer_Name" at 14.656,-21.806 h1.52
M16 Courtyards Bottom:
  text ".Layer_Name" at 14.656,-21.806 h1.52
Drill Drawing:
  circle w0.254: c3.033,193.508 r0.42
  circle w0.254: c3.033,193.508 r0.7
  circle w0.254: c3.033,174.607 r0.7
  lines w0.254: 2.333,161.306 2.333,161.656 2.683,162.006 2.333,162.356 2.333,162.706 2.683,162.706 3.033,162.356 3.383,162.706 3.733,162.706 3.733,162.356 3.383,162.006 3.733,161.656 3.733,161.306 3.383,161.306 3.033,161.656 2.683,161.306 2.333,161.306 ; 2.333,164.806 2.683,164.806 3.033,164.456 3.383,164.806 3.733,164.806 3.383,165.156 3.733,165.506 3.383,165.506 3.033,165.856 2.683,165.506 2.333,165.506 2.683,165.156 2.333,164.806 ; 2.333,167.606 3.033,167.956 3.733,167.606 3.383,168.306 3.733,169.006 3.033,168.656 2.333,169.006 2.683,168.306 2.333,167.606 ; 2.333,171.106 2.683,171.106 2.683,170.756 3.383,170.756 3.383,171.106 3.733,171.106 3.733,171.806 3.383,171.806 3.383,172.157 2.683,172.157 2.683,171.806 2.333,171.806 2.333,171.106 ; 2.333,178.457 3.733,178.457 3.033,177.057 2.333,178.457 ; 2.333,181.607 3.733,181.607 3.033,180.207 2.333,181.607 ; 2.333,184.058 3.033,183.358 3.733,184.058 3.033,184.758 2.333,184.058 ; 2.333,186.508 3.733,186.508 3.733,187.908 2.333,187.908 2.333,186.508 ; 2.333,189.658 3.733,189.658 3.733,191.058 2.333,191.058 2.333,189.658 ; 2.613,178.177 3.453,178.177 3.033,177.337 2.613,178.177 ; 2.613,186.788 3.453,186.788 3.453,187.628 2.613,187.628 2.613,186.788
  lines w0.305: 1.063,160.36 83.024,160.36 ; 1.063,195.014 83.024,195.014 ; 9.632,157.21 9.632,198.164 ; 18.057,157.21 18.057,198.164 ; 34.208,157.21 34.208,198.164 ; 40.781,157.21 40.781,198.164 ; 50.3,157.21 50.3,198.164 ; 68.653,157.21 68.653,198.164 ; 1.063,157.21 83.024,157.21 83.024,198.164 1.063,198.164 1.063,157.21
  text "Symbol" at 2.953,195.959 h1.83
  text "Quantity" at 10.577,195.959 h1.83
  text "Finished Hole Size" at 19.002,195.959 h1.83
  text "Plated" at 35.153,195.959 h1.83
  text "Hole Type" at 41.726,195.959 h1.83
  text "Drill Layer Pair" at 51.245,195.959 h1.83
  text "Hole Tolerance" at 69.598,195.959 h1.83
  text "32" at 10.577,192.808 h1.52
  text "7.87mil (0.200mm)" at 19.002,192.808 h1.52
  text "PTH" at 35.153,192.808 h1.52
  text "Round" at 41.726,192.808 h1.52
  text "Top Layer - Bottom Layer" at 51.245,192.808 h1.52
  text "1150" at 10.577,189.658 h1.52
  text "13.78mil (0.350mm)" at 19.002,189.658 h1.52
  text "PTH" at 35.153,189.658 h1.52
  text "Round" at 41.726,189.658 h1.52
  text "Top Layer - Bottom Layer" at 51.245,189.658 h1.52
  text "1" at 10.577,186.508 h1.52
  text "17.72mil (0.450mm)" at 19.002,186.508 h1.52
  text "PTH" at 35.153,186.508 h1.52
  text "Round" at 41.726,186.508 h1.52
  text "Top Layer - Bottom Layer" at 51.245,186.508 h1.52
  text "26" at 10.577,183.358 h1.52
  text "40.00mil (1.016mm)" at 19.002,183.358 h1.52
  text "PTH" at 35.153,183.358 h1.52
  text "Round" at 41.726,183.358 h1.52
  text "Top Layer - Bottom Layer" at 51.245,183.358 h1.52
  text "3" at 10.577,180.207 h1.52
  text "40.16mil (1.020mm)" at 19.002,180.207 h1.52
  text "PTH" at 35.153,180.207 h1.52
  text "Round" at 41.726,180.207 h1.52
  text "Top Layer - Bottom Layer" at 51.245,180.207 h1.52
  text "14" at 10.577,177.057 h1.52
  text "43.31mil (1.100mm)" at 19.002,177.057 h1.52
  text "PTH" at 35.153,177.057 h1.52
  text "Round" at 41.726,177.057 h1.52
  text "Top Layer - Bottom Layer" at 51.245,177.057 h1.52
  text "+/-1.97mil" at 69.598,177.057 h1.52
  text "2" at 10.577,173.907 h1.52
  text "51.18mil (1.300mm)" at 19.002,173.907 h1.52
  text "PTH" at 35.153,173.907 h1.52
  text "Round" at 41.726,173.907 h1.52
  text "Top Layer - Bottom Layer" at 51.245,173.907 h1.52
  text "16" at 10.577,170.756 h1.52
  text "62.99mil (1.600mm)" at 19.002,170.756 h1.52
  text "PTH" at 35.153,170.756 h1.52
  text "Round" at 41.726,170.756 h1.52
  text "Top Layer - Bottom Layer" at 51.245,170.756 h1.52
  text "+3.94mil/-0.00mil" at 69.598,170.756 h1.52
  text "4" at 10.577,167.606 h1.52
  text "62.99mil (1.600mm)" at 19.002,167.606 h1.52
  text "PTH" at 35.153,167.606 h1.52
  text "Round" at 41.726,167.606 h1.52
  text "Top Layer - Bottom Layer" at 51.245,167.606 h1.52
  text "2" at 10.577,164.456 h1.52
  text "63.00mil (1.600mm)" at 19.002,164.456 h1.52
  text "PTH" at 35.153,164.456 h1.52
  text "Round" at 41.726,164.456 h1.52
  text "Top Layer - Bottom Layer" at 51.245,164.456 h1.52
  text "2" at 10.577,161.306 h1.52
  text "23.62mil (0.600mm)" at 19.002,161.306 h1.52
  text "PTH" at 35.153,161.306 h1.52
  text "Slot" at 41.726,161.306 h1.52
  text "Top Layer - Bottom Layer" at 51.245,161.306 h1.52
  text "1252 Total" at 10.577,158.155 h1.52
  text "Slot definitions :" at 2.953,155.95 h1.52
  text "Routed Path Length" at 14.369,155.95 h1.52
  text "= Calculated from tool start centre position to tool end centre position." at 28.043,155.95 h1.52
  text "Hole Length" at 14.369,154.69 h1.52
  text "= Routed Path Length + Tool Size = Slot length as defined in the PCB layout" at 22.981,154.69 h1.52
  text ".Layer_Name" at 14.656,-21.806 h1.52
Mechanical 17:
  text ".Layer_Name" at 14.656,-21.806 h1.52
Mechanical 18:
  text ".Layer_Name" at 14.656,-21.806 h1.52
Mechanical 19:
  text ".Layer_Name" at 14.656,-21.806 h1.52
